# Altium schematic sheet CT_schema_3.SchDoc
size 205 x 169 mm
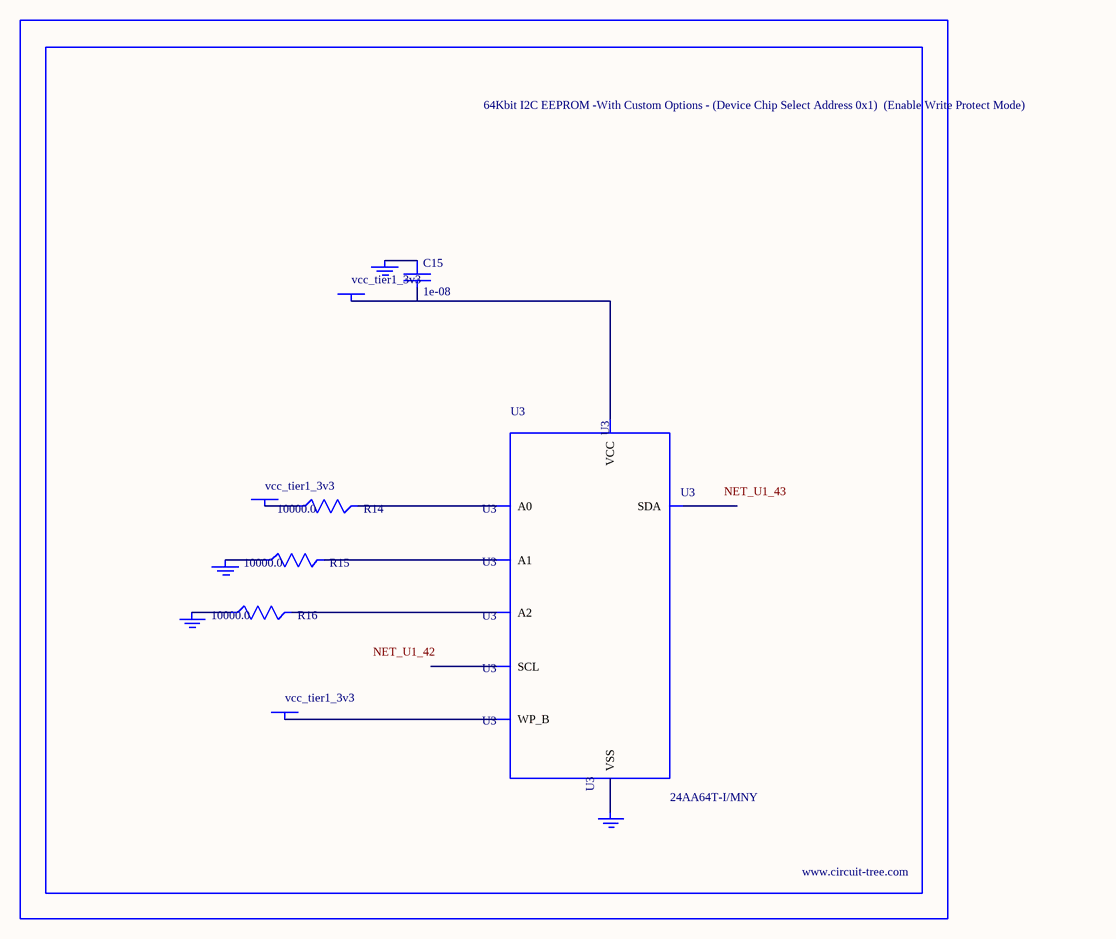
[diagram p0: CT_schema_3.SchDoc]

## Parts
BORDER2  (no value)
C15  1e-08  [C0402]
GND_INSTANCE_2_0  (no value)
GND_INSTANCE_2_1  (no value)
GND_INSTANCE_2_2  (no value)
GND_INSTANCE_2_3  (no value)
POWER_INSTANCE_2_0  vcc_tier1_3v3
POWER_INSTANCE_2_1  vcc_tier1_3v3
POWER_INSTANCE_2_2  vcc_tier1_3v3
R14  10000.0  [R0603]
R15  10000.0  [R0603]
R16  10000.0  [R0603]
U3  24AA64T-I/MNY  [TDFN-8/6MM]

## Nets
NetC15_1: C15.1 GND_INSTANCE_2_2.0(GND)
NetC15_2: C15.2 POWER_INSTANCE_2_2.0(PWR) U3.8(VCC)
NetGND_INSTANCE_2_0_0: GND_INSTANCE_2_0.0(GND) R15.1
NetGND_INSTANCE_2_1_0: GND_INSTANCE_2_1.0(GND) R16.1
NetGND_INSTANCE_2_3_0: GND_INSTANCE_2_3.0(GND) U3.4(VSS)
NetPOWER_INSTANCE_2_0_0: POWER_INSTANCE_2_0.0(PWR) R14.1
NetPOWER_INSTANCE_2_1_0: POWER_INSTANCE_2_1.0(PWR) U3.7(WP_B)
NetR14_2: R14.2 U3.1(A0)
NetR15_2: R15.2 U3.2(A1)
NetR16_2: R16.2 U3.3(A2)

Not connected (* = marked no-connect by the designer): U3 5(SDA) 6(SCL)

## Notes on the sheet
- Labels drawn without touching a wire or pin: NET_U1_42, NET_U1_43

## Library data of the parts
BORDER2 = BORDER_PAGE2
C15 = C0402C103K3RAC
GND_INSTANCE_2_0-GND_INSTANCE_2_3 = GND
POWER_INSTANCE_2_0-POWER_INSTANCE_2_2 = PWR
R14-R16 = RC0603JR-0710KL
